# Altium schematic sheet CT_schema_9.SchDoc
size 281 x 153 mm
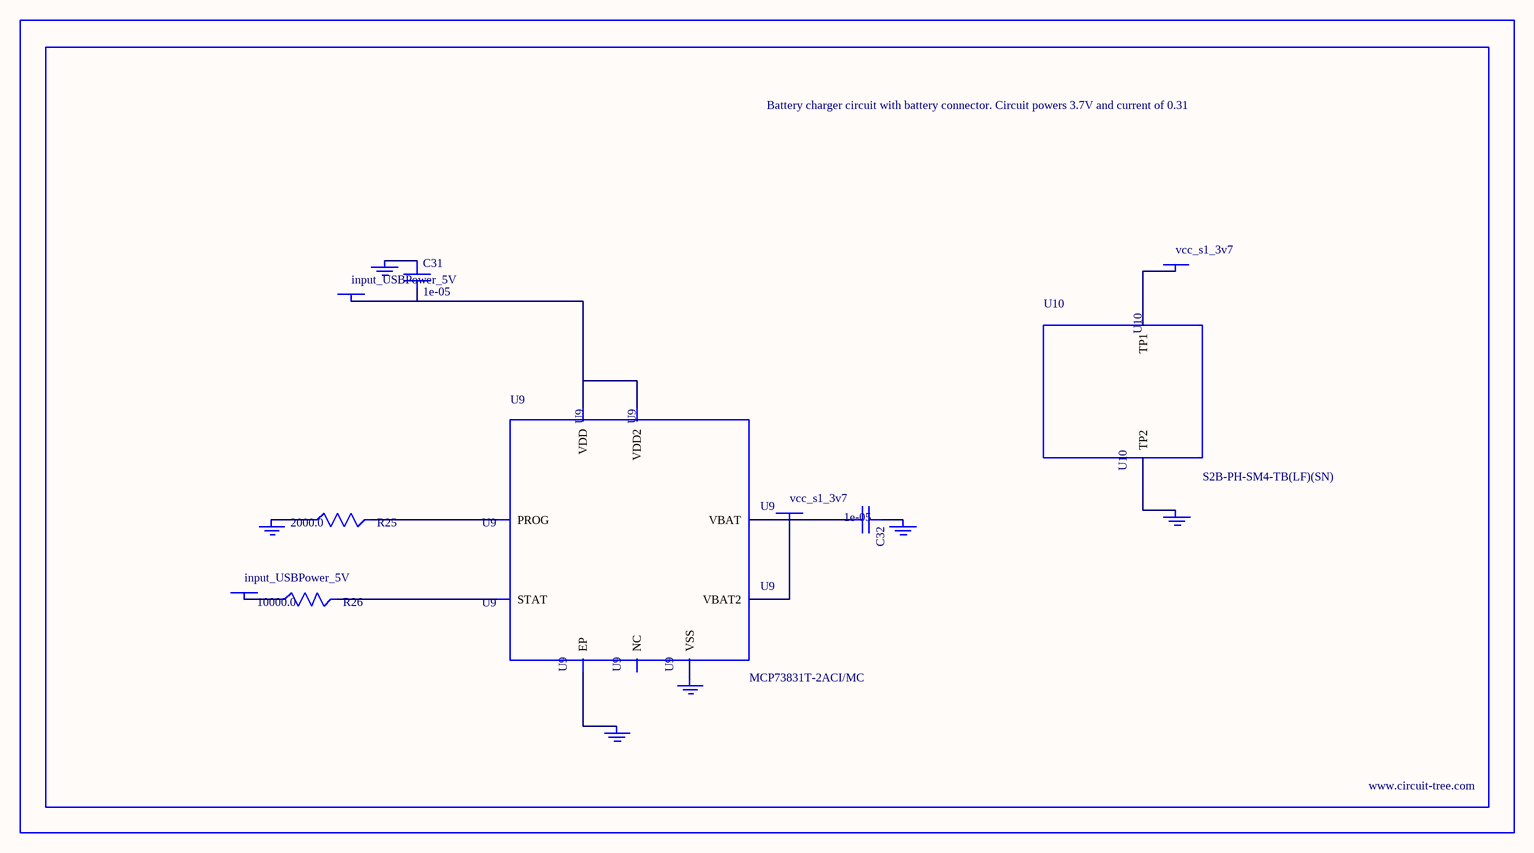
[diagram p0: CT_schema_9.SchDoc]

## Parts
BORDER8  (no value)
C31  1e-05  [C1206]
C32  1e-05  [C1206]
GND_INSTANCE_8_0  (no value)
GND_INSTANCE_8_1  (no value)
GND_INSTANCE_8_2  (no value)
GND_INSTANCE_8_3  (no value)
GND_INSTANCE_8_4  (no value)
GND_INSTANCE_8_5  (no value)
POWER_INSTANCE_8_0  input_USBPower_5V
POWER_INSTANCE_8_1  input_USBPower_5V
POWER_INSTANCE_8_2  vcc_s1_3v7
POWER_INSTANCE_8_3  vcc_s1_3v7
R25  2000.0  [R0603]
R26  10000.0  [R0603]
U9  MCP73831T-2ACI/MC  [DFN8_2X3MC]
U10  S2B-PH-SM4-TB(LF)(SN)  [JST-2-SMD]

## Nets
NetC31_1: C31.1 GND_INSTANCE_8_0.0(GND)
NetC31_2: C31.2 POWER_INSTANCE_8_0.0(PWR) U9.1(VDD) U9.2(VDD2)
NetC32_1: C32.1 GND_INSTANCE_8_1.0(GND)
NetC32_2: C32.2 POWER_INSTANCE_8_2.0(PWR) U9.3(VBAT) U9.4(VBAT2)
NetGND_INSTANCE_8_2_0: GND_INSTANCE_8_2.0(GND) R25.1
NetGND_INSTANCE_8_3_0: GND_INSTANCE_8_3.0(GND) U9.9(EP)
NetGND_INSTANCE_8_4_0: GND_INSTANCE_8_4.0(GND) U9.6(VSS)
NetGND_INSTANCE_8_5_0: GND_INSTANCE_8_5.0(GND) U10.2(TP2)
NetPOWER_INSTANCE_8_1_0: POWER_INSTANCE_8_1.0(PWR) R26.1
NetPOWER_INSTANCE_8_3_0: POWER_INSTANCE_8_3.0(PWR) U10.1(TP1)
NetR25_2: R25.2 U9.8(PROG)
NetR26_2: R26.2 U9.5(STAT)

Not connected (* = marked no-connect by the designer): U9 7(NC)

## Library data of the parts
BORDER8 = BORDER_PAGE8
C31 C32 = C1206C106K3RACTU
GND_INSTANCE_8_0-GND_INSTANCE_8_5 = GND
POWER_INSTANCE_8_0-POWER_INSTANCE_8_3 = PWR
R25 = RC0603JR-072KL
R26 = RC0603JR-0710KL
